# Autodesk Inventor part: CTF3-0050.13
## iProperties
Shininess: 64.0
Length Units: 11269
Angle Units: 11279
Time Units: 11290
Mass Units: 11283
Length Display Precision: 3
Angle Display Precision: 2
Compacted: True
Part Number: CTF3-0050.13
Document SubType Name: Modeling
Created: 2004-01
Designer: Lollo
Density: 0.0
Volumn: 0.0
Area: 0.0
PropertySet Name: Model Information
Control State: 0
Master: False
Checked Out: False
Author: Lollo
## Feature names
1. Estrusione1 [Extrusion]
2. Foro1 [Hole]
3. Serie circolare1 [Circular Pattern]
4. Smusso1 [Chamfer]
5. Foro2 [Hole]
6. Smusso2 [Chamfer]
7. Serie circolare2 [Circular Pattern]
